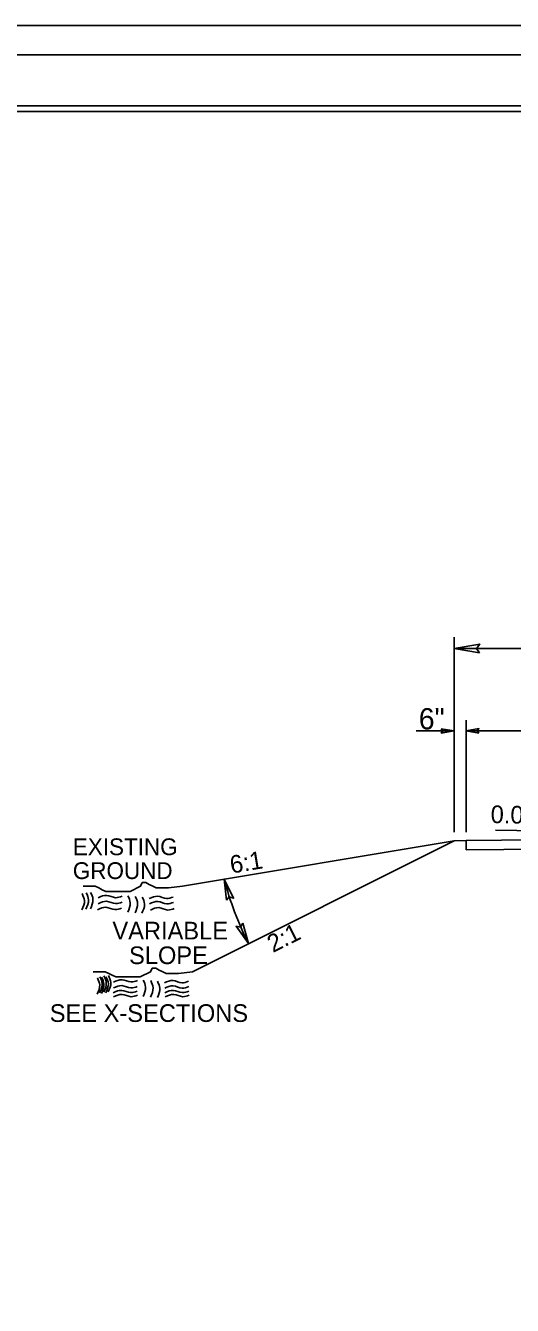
# Model space of a CAD drawing. Extents: x 2294455 to 2294795, y 719276 to 719941.
# Drawn here: x 2294548.7 to 2294591.8, y 719605.6 to 719718.8 of the extents above; entities that cross this region are included whole.
import ezdxf

# ---------------------------------------------------------------- set-up
doc = ezdxf.new("R2010")
doc.units = 0
for name, color, linetype in [('Default', 7, 'Continuous'), ('Old_Level_1', 7, 'Continuous'), ('Old_Level_11', 7, 'Continuous'), ('Old_Level_2', 7, 'Continuous'), ('Old_Level_3', 7, 'Continuous'), ('Sheet Plot Border Inside CELL', 7, 'Continuous'), ('Sheet Plot Border Outside CELL', 7, 'Continuous'), ('Sheet Typical CELL', 7, 'Continuous'), ('Typical Hinge Slope Arterial CELL', 7, 'Continuous')]:
    doc.layers.add(name, color=color, linetype=linetype)

msp = doc.modelspace()

# ---------------------------------------------------------------- linework, layer by layer
at = {"layer": 'Default'}
msp.add_lwpolyline([(2294454.52, 719716.17), (2294794.52, 719716.17), (2294794.52, 719496.17), (2294454.52, 719496.17)], close=True, dxfattribs=at)
at = {"layer": 'Old_Level_1'}
for p, q in [((2294594.05, 719647.57), (2294590.27, 719647.65)), ((2294563.48, 719635.13), (2294586.61, 719646.69)), ((2294586.61, 719646.69), (2294587.67, 719646.74)), ((2294587.67, 719646.74), (2294593.92, 719646.78)), ((2294587.69, 719645.91), (2294587.67, 719646.74)), ((2294587.69, 719645.91), (2294599.09, 719645.99))]:
    msp.add_line(p, q, dxfattribs=at)
at = {"layer": 'Old_Level_11'}
for p, q in [((2294586.61, 719647.45), (2294586.61, 719664.69)), ((2294586.61, 719663.69), (2294602.24, 719663.69)), ((2294587.67, 719647.45), (2294587.67, 719657.36)), ((2294586.61, 719656.42), (2294583.26, 719656.42)), ((2294599.09, 719656.42), (2294587.67, 719656.42))]:
    msp.add_line(p, q, dxfattribs=at)
for points in [[(2294588.86, 719663.31), (2294586.61, 719663.69), (2294588.87, 719664.09), (2294588.58, 719663.69)], [(2294585.48, 719656.61), (2294586.61, 719656.42), (2294585.48, 719656.22), (2294585.62, 719656.42)], [(2294588.79, 719656.22), (2294587.67, 719656.42), (2294588.8, 719656.62), (2294588.66, 719656.42)], [(2294566.5, 719641.45), (2294566.29, 719643.31), (2294567.12, 719641.62), (2294566.74, 719641.76)], [(2294567.93, 719639.41), (2294568.43, 719637.61), (2294567.34, 719639.15), (2294567.74, 719639.07)]]:
    msp.add_lwpolyline(points, close=True, dxfattribs=at)
at = {"layer": 'Old_Level_2'}
msp.add_line((2294454.52, 719716.17), (2294794.52, 719716.17), dxfattribs=at)
for points in [[(2294553.73, 719642.03), (2294553.94, 719641.41), (2294553.71, 719640.59)], [(2294553.73, 719642.03), (2294553.94, 719641.41), (2294553.71, 719640.59)], [(2294554.09, 719642.1), (2294554.3, 719641.48), (2294554.07, 719640.66)], [(2294554.09, 719642.1), (2294554.3, 719641.48), (2294554.07, 719640.66)], [(2294554.48, 719642.14), (2294554.69, 719641.52), (2294554.47, 719640.7)], [(2294554.48, 719642.14), (2294554.69, 719641.52), (2294554.47, 719640.7)], [(2294555.15, 719641.66), (2294555.9, 719641.88), (2294556.69, 719641.67), (2294557.26, 719641.8)], [(2294555.15, 719641.66), (2294555.9, 719641.88), (2294556.69, 719641.67), (2294557.26, 719641.8)], [(2294557.78, 719641.84), (2294557.98, 719641.22), (2294557.76, 719640.39)], [(2294557.78, 719641.84), (2294557.98, 719641.22), (2294557.76, 719640.39)], [(2294558.43, 719641.79), (2294558.64, 719641.16), (2294558.42, 719640.34)], [(2294558.43, 719641.79), (2294558.64, 719641.16), (2294558.42, 719640.34)], [(2294559.04, 719641.73), (2294559.25, 719641.11), (2294559.02, 719640.29)], [(2294559.66, 719641.59), (2294560.41, 719641.8), (2294561.2, 719641.6), (2294561.78, 719641.73)], [(2294559.66, 719641.59), (2294560.41, 719641.8), (2294561.2, 719641.6), (2294561.78, 719641.73)], [(2294555.08, 719640.61), (2294555.84, 719640.82), (2294556.63, 719640.62), (2294557.21, 719640.75)], [(2294555.08, 719640.61), (2294555.84, 719640.82), (2294556.63, 719640.62), (2294557.21, 719640.75)], [(2294555.14, 719641.14), (2294555.9, 719641.35), (2294556.69, 719641.15), (2294557.26, 719641.28)], [(2294555.14, 719641.14), (2294555.9, 719641.35), (2294556.69, 719641.15), (2294557.26, 719641.28)], [(2294559.68, 719641.12), (2294560.43, 719641.33), (2294561.22, 719641.13), (2294561.8, 719641.26)], [(2294559.68, 719641.12), (2294560.43, 719641.33), (2294561.22, 719641.13), (2294561.8, 719641.26)], [(2294559.76, 719640.57), (2294560.51, 719640.79), (2294561.3, 719640.58), (2294561.88, 719640.71)], [(2294559.76, 719640.57), (2294560.51, 719640.79), (2294561.3, 719640.58), (2294561.88, 719640.71)], [(2294555.66, 719634.76), (2294555.87, 719634.14), (2294555.65, 719633.31)], [(2294556.05, 719634.8), (2294556.27, 719634.18), (2294556.04, 719633.36)], [(2294555.08, 719634.58), (2294555.29, 719633.96), (2294555.07, 719633.14)], [(2294555.3, 719634.69), (2294555.51, 719634.07), (2294555.28, 719633.25)], [(2294555.45, 719634.65), (2294555.66, 719634.03), (2294555.43, 719633.21)], [(2294555.84, 719634.69), (2294556.05, 719634.07), (2294555.82, 719633.25)], [(2294556.5, 719634.21), (2294557.25, 719634.42), (2294558.05, 719634.22), (2294558.62, 719634.35)], [(2294556.5, 719634.21), (2294557.25, 719634.42), (2294558.05, 719634.22), (2294558.62, 719634.35)], [(2294556.5, 719633.69), (2294557.25, 719633.9), (2294558.04, 719633.69), (2294558.61, 719633.82)], [(2294556.5, 719633.69), (2294557.25, 719633.9), (2294558.04, 719633.69), (2294558.61, 719633.82)], [(2294559.13, 719634.39), (2294559.34, 719633.77), (2294559.12, 719632.94)], [(2294559.13, 719634.39), (2294559.34, 719633.77), (2294559.12, 719632.94)], [(2294559.79, 719634.34), (2294560, 719633.71), (2294559.77, 719632.89)], [(2294559.79, 719634.34), (2294560, 719633.71), (2294559.77, 719632.89)], [(2294560.39, 719634.28), (2294560.6, 719633.66), (2294560.38, 719632.84)], [(2294560.39, 719634.28), (2294560.6, 719633.66), (2294560.38, 719632.84)], [(2294561.01, 719634.14), (2294561.77, 719634.35), (2294562.56, 719634.15), (2294563.13, 719634.28)], [(2294561.03, 719633.67), (2294561.79, 719633.88), (2294562.58, 719633.68), (2294563.15, 719633.81)], [(2294561.03, 719633.67), (2294561.79, 719633.88), (2294562.58, 719633.68), (2294563.15, 719633.81)], [(2294556.47, 719633.27), (2294557.22, 719633.48), (2294558.02, 719633.28), (2294558.59, 719633.41)], [(2294556.47, 719633.27), (2294557.22, 719633.48), (2294558.02, 719633.28), (2294558.59, 719633.41)], [(2294556.51, 719632.91), (2294557.26, 719633.12), (2294558.06, 719632.92), (2294558.63, 719633.05)], [(2294561.04, 719633.27), (2294561.79, 719633.48), (2294562.58, 719633.28), (2294563.16, 719633.41)], [(2294561.04, 719633.27), (2294561.79, 719633.48), (2294562.58, 719633.28), (2294563.16, 719633.41)], [(2294561.08, 719632.91), (2294561.83, 719633.12), (2294562.63, 719632.92), (2294563.2, 719633.05)]]:
    msp.add_spline(points, degree=3, dxfattribs=at)
at = {"layer": 'Sheet Plot Border Inside CELL'}
msp.add_lwpolyline([(2294790.42, 719711.68), (2294457.12, 719711.68), (2294457.12, 719500.66), (2294790.42, 719500.66)], close=True, dxfattribs=at)
at = {"layer": 'Sheet Plot Border Outside CELL'}
for points in [[(2294793.79, 719718.76), (2294456.99, 719718.76), (2294456.99, 719498.76), (2294793.79, 719498.76)], [(2294454.52, 719496.17), (2294791.32, 719496.17), (2294791.32, 719716.17), (2294454.52, 719716.17)], [(2294794.52, 719716.17), (2294454.52, 719716.17), (2294454.52, 719496.17), (2294794.52, 719496.17)]]:
    msp.add_lwpolyline(points, close=True, dxfattribs=at)
at = {"layer": 'Sheet Typical CELL'}
msp.add_lwpolyline([(2294787.92, 719711.17), (2294487.92, 719711.17), (2294487.92, 719501.17), (2294787.92, 719501.17)], close=True, dxfattribs=at)
at = {"layer": 'Typical Hinge Slope Arterial CELL'}
msp.add_line((2294562.59, 719642.69), (2294586.61, 719646.69), dxfattribs=at)
for points in [[(2294562.59, 719642.69), (2294561.36, 719642.54), (2294561.05, 719642.54), (2294560.59, 719642.54), (2294560.28, 719642.54), (2294559.98, 719642.69), (2294559.67, 719642.85), (2294559.36, 719643), (2294559.05, 719643), (2294558.9, 719642.69), (2294558.59, 719642.54), (2294558.28, 719642.38), (2294557.97, 719642.23), (2294557.67, 719642.23), (2294557.36, 719642.23), (2294557.05, 719642.23), (2294556.74, 719642.23), (2294556.43, 719642.23), (2294556.13, 719642.23), (2294555.82, 719642.23), (2294555.51, 719642.38), (2294555.2, 719642.54), (2294554.89, 719642.69), (2294554.43, 719642.69), (2294554.12, 719642.69), (2294553.82, 719642.69)], [(2294563.48, 719635.13), (2294562.24, 719634.98), (2294561.94, 719634.98), (2294561.47, 719634.98), (2294561.17, 719634.98), (2294560.86, 719635.13), (2294560.55, 719635.28), (2294560.24, 719635.44), (2294559.93, 719635.44), (2294559.78, 719635.13), (2294559.47, 719634.98), (2294559.16, 719634.82), (2294558.86, 719634.67), (2294558.55, 719634.67), (2294558.24, 719634.67), (2294557.93, 719634.67), (2294557.62, 719634.67), (2294557.32, 719634.67), (2294557.01, 719634.67), (2294556.7, 719634.67), (2294556.39, 719634.82), (2294556.08, 719634.98), (2294555.78, 719635.13), (2294555.31, 719635.13), (2294555.01, 719635.13), (2294554.7, 719635.13)]]:
    msp.add_lwpolyline(points, dxfattribs=at)
msp.add_arc((2294594.31, 719650.56), 28.94, 194.5, 206.5651, dxfattribs=at)

# ---------------------------------------------------------------- texts
at = {"layer": 'Old_Level_1'}
for s, height, rotation, p in [('EXISTING', 1.484, 360, (2294552.91, 719645.43)), ('6:1', 1.562, 9.4623, (2294566.93, 719643.8)), ('GROUND', 1.484, 360, (2294552.91, 719643.32)), ('2:1', 1.562, 26.5651, (2294570.59, 719636.78)), ('SEE X-SECTIONS', 1.5625, 360, (2294550.87, 719630.69))]:
    msp.add_text(s, height=height, rotation=rotation, dxfattribs=at).set_placement(p)
at = {"layer": 'Old_Level_11'}
msp.add_text('6"', height=1.875, dxfattribs=at).set_placement((2294583.49, 719656.55))
at = {"layer": 'Old_Level_3'}
msp.add_text('0.02', height=1.562, rotation=358.8543, dxfattribs=at).set_placement((2294589.83, 719648.27))
at = {"layer": 'Typical Hinge Slope Arterial CELL'}
for s, p in [('VARIABLE ', (2294556.41, 719637.98)), ('SLOPE', (2294557.88, 719635.8))]:
    msp.add_text(s, height=1.562, dxfattribs=at).set_placement(p)

doc.saveas('drawing.dxf')
